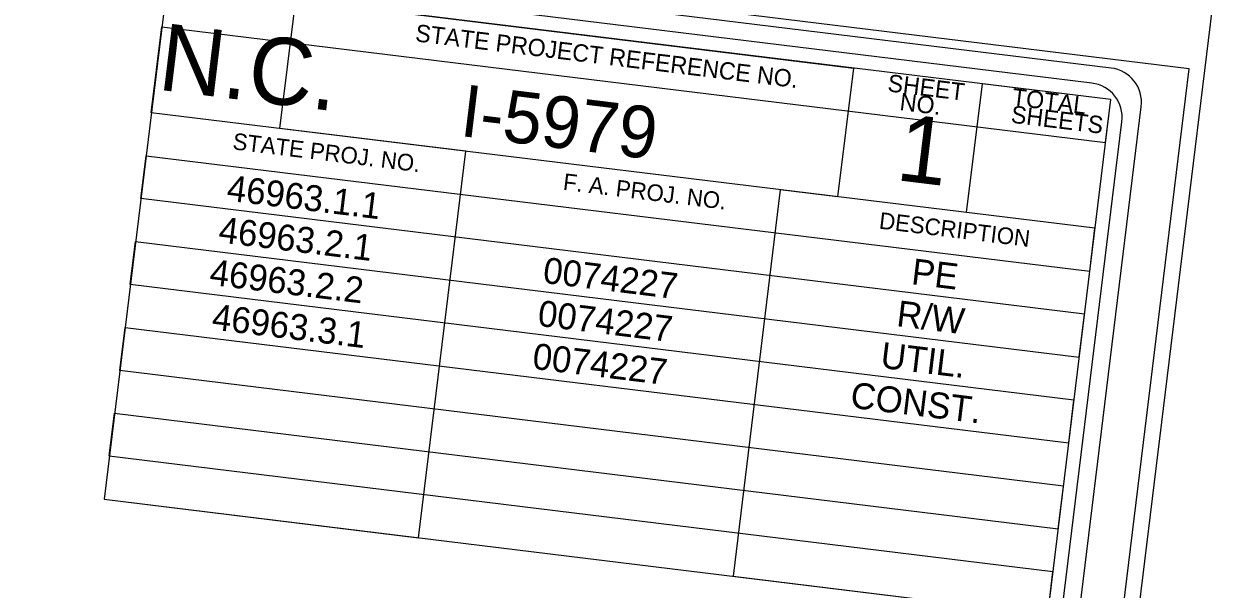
# Model space of a CAD drawing. Extents: x 1756435 to 1766932, y 416863 to 426859.
# Drawn here: x 1765186 to 1766576, y 425338 to 425997 of the extents above; entities that cross this region are included whole.
import ezdxf

# ---------------------------------------------------------------- set-up
doc = ezdxf.new("R2010")
doc.units = 0
for name, color, linetype in [('Sheet Data Field CELL', 7, 'Continuous'), ('Sheet Plot Border Inside CELL', 7, 'Continuous'), ('Sheet Plot Border Outside CELL', 7, 'Continuous'), ('Sheet Title CELL', 7, 'Continuous')]:
    doc.layers.add(name, color=color, linetype=linetype)

msp = doc.modelspace()

# ---------------------------------------------------------------- linework, layer by layer
at = {"layer": 'Sheet Plot Border Inside CELL'}
msp.add_lwpolyline([(1759349.9, 422533.3), (1766029.4, 421715.9), (1766546.9, 425944.9), (1759867.4, 426762.2)], close=True, dxfattribs=at)
at = {"layer": 'Sheet Plot Border Outside CELL'}
msp.add_lwpolyline([(1766576, 426032.6), (1759826.3, 426858.6), (1759286.8, 422449.7), (1766036.5, 421623.8)], close=True, dxfattribs=at)
at = {"layer": 'Sheet Title CELL'}
for points in [[(1766455.5, 425945.7), (1760523.5, 426671.6)], [(1766433, 425928.1), (1760741.5, 426624.6)], [(1765279.3, 425442.8), (1766381.5, 425308), (1766387.6, 425358), (1765285.4, 425492.9), (1765291.5, 425543), (1766393.8, 425408.1), (1766399.9, 425458.2), (1765297.7, 425593.1), (1765303.8, 425643.2), (1766406, 425508.4), (1766412.2, 425558.5), (1765309.9, 425693.3), (1765316.1, 425743.4), (1766418.3, 425608.6), (1766424.4, 425658.6), (1765322.2, 425793.5), (1765328.3, 425843.6), (1766430.6, 425708.7), (1766436.7, 425758.9), (1765334.5, 425893.7), (1765346.7, 425993.9), (1766449, 425859.1), (1766455.1, 425909.2), (1765352.9, 426044), (1765279.3, 425442.8), (1765646.6, 425397.8), (1765701.8, 425848.7), (1765484.8, 425875.3), (1765503.2, 426025.7), (1766154.5, 425945.9), (1766136.1, 425795.6), (1766069.2, 425803.8), (1766014, 425352.9), (1766381.5, 425308), (1766455.1, 425909.2), (1766304.8, 425927.6), (1766286.4, 425777.2)], [(1765985.5, 421772.4), (1766490.7, 425900.7)], [(1766058.6, 422536.3), (1766468.2, 425883.2)]]:
    msp.add_lwpolyline(points, dxfattribs=at)
for centre in [(1766450.6, 425905.8), (1766428.1, 425888.2)]:
    msp.add_arc(centre, 40.4, 353.0234, 83.0234, dxfattribs=at)

# ---------------------------------------------------------------- texts
at = {"layer": 'Sheet Data Field CELL'}
for s, height, p in [('I-5979', 60.57, (1765693.6, 425866.8)), ('46963.1.1', 30.29, (1765421.6, 425791.3)), ('46963.2.1', 30.29, (1765412, 425742.6)), ('46963.2.2', 30.29, (1765401.5, 425693.1)), ('0074227', 30.29, (1765790.9, 425695.3)), ('PE', 30.29, (1766221.3, 425693.8)), ('46963.3.1', 30.29, (1765404.2, 425640.9)), ('0074227', 30.29, (1765784.8, 425645.2)), ('R/W', 30.29, (1766204, 425644.8)), ('0074227', 30.29, (1765778.6, 425595.1)), ('UTIL.', 30.29, (1766185.2, 425596.2)), ('CONST.', 30.29, (1766150, 425549.7))]:
    msp.add_text(s, height=height, rotation=353.0234, dxfattribs=at).set_placement(p)
at = {"layer": 'Sheet Title CELL'}
for s, height, p in [('N.C.', 78.14, (1765340.8, 425920.8)), ('STATE PROJECT REFERENCE NO.', 20.189, (1765642, 425977.1)), ('SHEET', 20.19, (1766193.7, 425918.7)), ('NO.', 20.19, (1766207.9, 425896.9)), ('TOTAL', 20.19, (1766338.9, 425902.4)), ('SHEETS', 20.19, (1766337.8, 425882.2)), ('1', 78.1, (1766203, 425815.3)), ('STATE PROJ. NO.', 19.382, (1765428.7, 425851.1)), ('F. A. PROJ. NO.', 19.382, (1765814.7, 425803.9)), ('DESCRIPTION', 19.382, (1766183.8, 425758.6))]:
    msp.add_text(s, height=height, rotation=353.0234, dxfattribs=at).set_placement(p)

doc.saveas('drawing.dxf')
